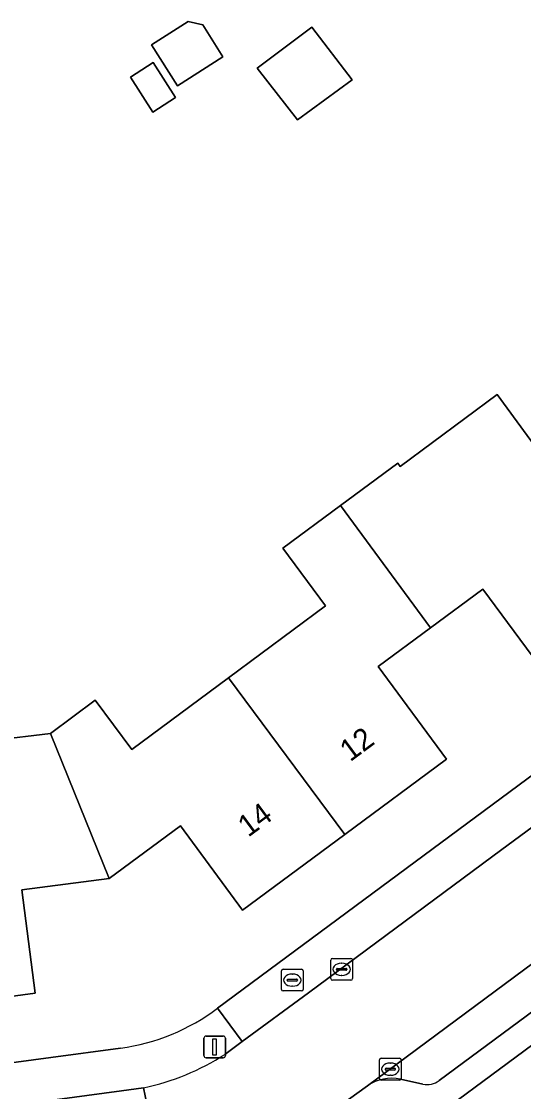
# Model space of a CAD drawing. Extents: x 163426 to 164192, y 380329 to 381641.
# Drawn here: x 163640.74 to 163663.86, y 381284.84 to 381334.09 of the extents above; entities that cross this region are included whole.
import ezdxf

# ---------------------------------------------------------------- set-up
doc = ezdxf.new("R2010")
doc.units = 0
for name, color, linetype in [('IMGEO_Brandkraan', 7, 'Continuous'), ('IMGEO_Erf', 7, 'Continuous'), ('IMGEO_Kolk', 7, 'Continuous'), ('IMGEO_Lichtmast', 7, 'Continuous'), ('IMGEO_Pand', 7, 'Continuous'), ('IMGEO_Pand_nummerreeks', 7, 'Continuous'), ('IMGEO_Parkeervlak_open', 7, 'Continuous'), ('IMGEO_Rijbaan_lokaal_open', 7, 'Continuous'), ('IMGEO_Voetpad_open', 7, 'Continuous')]:
    doc.layers.add(name, color=color, linetype=linetype)

msp = doc.modelspace()

# ---------------------------------------------------------------- linework, layer by layer
at = {"layer": 'IMGEO_Brandkraan'}
for p, q in [((163652.71, 381289.542), (163652.71, 381290.394)), ((163652.785, 381290.468), (163653.637, 381290.468)), ((163653.198, 381290.248), (163653.223, 381290.248)), ((163653.711, 381290.394), (163653.711, 381289.542)), ((163652.969, 381289.962), (163652.969, 381289.974)), ((163653.407, 381289.925), (163653.009, 381289.925)), ((163653.012, 381290.011), (163653.41, 381290.011)), ((163653.221, 381289.688), (163653.196, 381289.688)), ((163653.453, 381289.974), (163653.453, 381289.962)), ((163653.637, 381289.468), (163652.785, 381289.468))]:
    msp.add_line(p, q, dxfattribs=at)
for points in [[(163652.71, 381289.542), (163652.71, 381290.394)], [(163652.785, 381290.468), (163653.637, 381290.468)], [(163653.711, 381290.394), (163653.711, 381289.542)], [(163653.637, 381289.468), (163652.785, 381289.468)]]:
    msp.add_lwpolyline(points, dxfattribs=at)
for centre, radius, start, end in [((163652.787, 381290.392), 0.0765, 91.552, 178.448), ((163652.787, 381290.392), 0.0765, 91.552, 178.448), ((163653.635, 381290.392), 0.0765, 1.552, 88.448), ((163653.635, 381290.392), 0.0765, 1.552, 88.448), ((163653.009, 381289.971), 0.0403, 85.8775, 175.7526), ((163653.006, 381289.961), 0.0366, 178.938, 274.7102), ((163653.41, 381289.968), 0.043, 264.8664, 352.4533), ((163653.414, 381289.973), 0.0386, 1.7309, 96.639), ((163652.787, 381289.544), 0.0765, 181.552, 268.448), ((163652.787, 381289.544), 0.0765, 181.552, 268.448), ((163653.635, 381289.544), 0.0765, 271.552, 358.448), ((163653.635, 381289.544), 0.0765, 271.552, 358.448)]:
    msp.add_arc(centre, radius, start, end, dxfattribs=at)
for centre, major_axis, ratio, start_param, end_param in [((163653.197, 381289.968), (-0.387, 0.002), 0.722429, 4.712389, 7.853982), ((163653.222, 381289.968), (-0.39, 0.002), 0.717154, 1.570796, 4.712389)]:
    msp.add_ellipse(centre, major_axis=major_axis, ratio=ratio, start_param=start_param, end_param=end_param, dxfattribs=at)
at = {"layer": 'IMGEO_Erf'}
for points in [[(163647.921, 381331.13), (163646.723, 381333.013), (163648.421, 381334.093), (163649.086, 381333.928), (163650.018, 381332.464)], [(163654.105, 381333.835), (163655.963, 381331.405), (163653.457, 381329.566), (163651.599, 381331.939)], [(163645.76, 381331.53), (163646.807, 381332.196), (163647.83, 381330.589), (163646.783, 381329.923)]]:
    msp.add_lwpolyline(points, close=True, dxfattribs=at)
for points in [[(163649.769, 381288.678), (163692.92, 381320.603), (163703.68, 381328.564)], [(163740.553, 381295.871), (163741.259, 381296.424), (163738.778, 381299.792), (163718.602, 381327.167), (163657.027, 381281.631)], [(163639.5, 381301.01), (163642.07, 381301.32), (163644.14, 381302.85), (163645.82, 381300.582), (163650.279, 381303.886), (163654.746, 381307.196), (163652.78, 381309.85), (163655.428, 381311.81), (163658.069, 381313.765), (163658.184, 381313.609), (163662.649, 381316.914), (163664.494, 381314.412)], [(163665.136, 381303.706), (163661.986, 381307.964), (163659.576, 381306.181), (163657.166, 381304.398), (163660.316, 381300.14), (163655.624, 381296.669), (163650.92, 381293.19), (163648.06, 381297.07), (163644.78, 381294.65), (163640.75, 381294.12), (163641.37, 381289.36), (163635.572, 381288.579)], [(163588.634, 381279.227), (163596.717, 381280.313), (163605.786, 381281.532), (163642.098, 381286.411), (163645.301, 381286.841)]]:
    msp.add_lwpolyline(points, dxfattribs=at)
msp.add_arc((163644.05, 381296.235), 9.477, 277.5829, 307.1168, dxfattribs=at)
at = {"layer": 'IMGEO_Kolk'}
for p, q in [((163654.982, 381290.038), (163654.982, 381290.89)), ((163655.057, 381290.964), (163655.909, 381290.964)), ((163655.47, 381290.744), (163655.495, 381290.744)), ((163655.983, 381290.89), (163655.983, 381290.038)), ((163655.241, 381290.458), (163655.241, 381290.47)), ((163655.679, 381290.421), (163655.281, 381290.421)), ((163655.284, 381290.507), (163655.682, 381290.507)), ((163655.493, 381290.184), (163655.468, 381290.184)), ((163655.725, 381290.47), (163655.725, 381290.458)), ((163655.909, 381289.964), (163655.057, 381289.964)), ((163657.224, 381285.443), (163657.224, 381286.295)), ((163657.299, 381286.369), (163658.151, 381286.369)), ((163657.712, 381286.149), (163657.737, 381286.149)), ((163658.225, 381286.295), (163658.225, 381285.443)), ((163657.483, 381285.863), (163657.483, 381285.875)), ((163657.921, 381285.826), (163657.523, 381285.826)), ((163657.526, 381285.912), (163657.924, 381285.912)), ((163657.967, 381285.875), (163657.967, 381285.863)), ((163658.151, 381285.369), (163657.299, 381285.369)), ((163657.735, 381285.589), (163657.71, 381285.589))]:
    msp.add_line(p, q, dxfattribs=at)
for points in [[(163654.982, 381290.038), (163654.982, 381290.89)], [(163655.057, 381290.964), (163655.909, 381290.964)], [(163655.983, 381290.89), (163655.983, 381290.038)], [(163655.909, 381289.964), (163655.057, 381289.964)], [(163657.224, 381285.443), (163657.224, 381286.295)], [(163657.299, 381286.369), (163658.151, 381286.369)], [(163658.225, 381286.295), (163658.225, 381285.443)], [(163658.151, 381285.369), (163657.299, 381285.369)]]:
    msp.add_lwpolyline(points, dxfattribs=at)
for centre, radius, start, end in [((163655.059, 381290.888), 0.0765, 91.552, 178.448), ((163655.059, 381290.888), 0.0765, 91.552, 178.448), ((163655.907, 381290.888), 0.0765, 1.552, 88.448), ((163655.907, 381290.888), 0.0765, 1.552, 88.448), ((163655.281, 381290.467), 0.0403, 85.8775, 175.7526), ((163655.278, 381290.457), 0.0366, 178.938, 274.7102), ((163655.682, 381290.464), 0.043, 264.8664, 352.4533), ((163655.686, 381290.469), 0.0386, 1.7309, 96.639), ((163655.059, 381290.04), 0.0765, 181.552, 268.448), ((163655.059, 381290.04), 0.0765, 181.552, 268.448), ((163655.907, 381290.04), 0.0765, 271.552, 358.448), ((163655.907, 381290.04), 0.0765, 271.552, 358.448), ((163657.301, 381286.293), 0.0765, 91.552, 178.448), ((163657.301, 381286.293), 0.0765, 91.552, 178.448), ((163658.149, 381286.293), 0.0765, 1.552, 88.448), ((163658.149, 381286.293), 0.0765, 1.552, 88.448), ((163657.523, 381285.872), 0.0403, 85.8775, 175.7526), ((163657.52, 381285.862), 0.0366, 178.938, 274.7102), ((163657.924, 381285.869), 0.043, 264.8664, 352.4533), ((163657.928, 381285.874), 0.0386, 1.7309, 96.639), ((163657.301, 381285.445), 0.0765, 181.552, 268.448), ((163657.301, 381285.445), 0.0765, 181.552, 268.448), ((163658.149, 381285.445), 0.0765, 271.552, 358.448), ((163658.149, 381285.445), 0.0765, 271.552, 358.448)]:
    msp.add_arc(centre, radius, start, end, dxfattribs=at)
for centre, major_axis, ratio, start_param, end_param in [((163655.469, 381290.464), (-0.387, 0.002), 0.722429, 4.712389, 7.853982), ((163655.494, 381290.464), (-0.39, 0.002), 0.717154, 1.570796, 4.712389), ((163657.711, 381285.869), (-0.387, 0.002), 0.722429, 4.712389, 7.853982), ((163657.736, 381285.869), (-0.39, 0.002), 0.717154, 1.570796, 4.712389)]:
    msp.add_ellipse(centre, major_axis=major_axis, ratio=ratio, start_param=start_param, end_param=end_param, dxfattribs=at)
at = {"layer": 'IMGEO_Lichtmast'}
for p, q in [((163649.137, 381286.491), (163649.137, 381287.291)), ((163649.137, 381287.291), (163649.137, 381286.491)), ((163649.237, 381287.391), (163650.027, 381287.391)), ((163650.027, 381287.391), (163649.237, 381287.391)), ((163650.127, 381287.291), (163650.127, 381286.491)), ((163650.127, 381286.491), (163650.127, 381287.291)), ((163650.027, 381286.391), (163649.237, 381286.391)), ((163649.237, 381286.391), (163650.027, 381286.391))]:
    msp.add_line(p, q, dxfattribs=at)
msp.add_lwpolyline([(163649.557, 381287.266), (163649.707, 381287.266), (163649.707, 381286.516), (163649.557, 381286.516), (163649.557, 381287.266)], dxfattribs=at)
for centre, start, end in [((163649.237, 381287.291), 90, 180), ((163649.237, 381287.291), 90, 180), ((163650.027, 381287.291), 0, 90), ((163650.027, 381287.291), 360, 90), ((163649.237, 381286.491), 180, 270), ((163649.237, 381286.491), 180, 270), ((163650.027, 381286.491), 270, 0), ((163650.027, 381286.491), 270, 0)]:
    msp.add_arc(centre, 0.1, start, end, dxfattribs=at)
at = {"layer": 'IMGEO_Pand'}
for points in [[(163649.086, 381333.928), (163648.421, 381334.093), (163646.723, 381333.013), (163647.921, 381331.13), (163650.018, 381332.464)], [(163654.105, 381333.835), (163651.599, 381331.939), (163653.457, 381329.566), (163655.963, 381331.405)], [(163645.76, 381331.53), (163646.783, 381329.923), (163647.83, 381330.589), (163646.807, 381332.196)], [(163664.494, 381314.412), (163662.649, 381316.914), (163658.184, 381313.609), (163658.069, 381313.765), (163655.428, 381311.81), (163659.576, 381306.181), (163661.986, 381307.964), (163665.136, 381303.706), (163669.828, 381307.177)], [(163655.624, 381296.669), (163660.316, 381300.14), (163657.166, 381304.398), (163659.576, 381306.181), (163655.428, 381311.81), (163652.78, 381309.85), (163654.746, 381307.196), (163650.279, 381303.886)], [(163650.279, 381303.886), (163645.82, 381300.582), (163644.14, 381302.85), (163642.07, 381301.32), (163644.78, 381294.65), (163648.06, 381297.07), (163650.92, 381293.19), (163655.624, 381296.669)], [(163642.07, 381301.32), (163639.5, 381301.01), (163639.372, 381301.961), (163633.908, 381301.222), (163633.97, 381300.741), (163634.391, 381297.478), (163635.572, 381288.579), (163641.37, 381289.36), (163640.75, 381294.12), (163644.78, 381294.65)]]:
    msp.add_lwpolyline(points, close=True, dxfattribs=at)
at = {"layer": 'IMGEO_Parkeervlak_open'}
for points in [[(163710.833, 381325.231), (163656.677, 381285.107)], [(163659.971, 381285.341), (163672.822, 381294.849), (163675.849, 381297.088), (163684.721, 381303.652), (163690.817, 381308.162), (163698.807, 381314.074), (163704.911, 381318.588), (163709.791, 381322.2)], [(163658.194, 381285.401), (163659.227, 381285.18)]]:
    msp.add_lwpolyline(points, dxfattribs=at)
for centre, radius, start, end in [((163657.771, 381283.524), 1.924, 77.2983, 124.638), ((163659.421, 381286.081), 0.922, 257.8151, 306.6057)]:
    msp.add_arc(centre, radius, start, end, dxfattribs=at)
at = {"layer": 'IMGEO_Rijbaan_lokaal_open'}
for points in [[(163656.677, 381285.107), (163710.833, 381325.231), (163712.71, 381326.586), (163715.289, 381328.447), (163711.359, 381331.806), (163694.161, 381319.1), (163691.113, 381316.849), (163682.665, 381310.607), (163677.183, 381306.556), (163668.338, 381300.021), (163662.864, 381295.976), (163653.949, 381289.389), (163650.902, 381287.137), (163650.108, 381286.551)], [(163638.12, 381278.876), (163641.866, 381279.344), (163647.21, 381280.954), (163646.365, 381285.009), (163645.343, 381284.872), (163641.583, 381284.366), (163630.219, 381282.832), (163623.472, 381281.919), (163613.137, 381280.536), (163607.081, 381279.743), (163589.884, 381277.411)], [(163646.365, 381285.009), (163647.21, 381280.954), (163654.075, 381283.021), (163655.038, 381283.926), (163656.677, 381285.107)]]:
    msp.add_lwpolyline(points, dxfattribs=at)
msp.add_arc((163644.023, 381296.008), 11.246, 282.021, 302.7593, dxfattribs=at)
at = {"layer": 'IMGEO_Voetpad_open'}
msp.add_lwpolyline([(163682.665, 381310.607), (163691.113, 381316.849), (163694.161, 381319.1), (163711.359, 381331.806), (163710.193, 381333.382), (163703.68, 381328.564), (163692.92, 381320.603), (163649.769, 381288.678), (163650.902, 381287.137), (163653.949, 381289.389), (163662.864, 381295.976), (163668.338, 381300.021), (163677.183, 381306.556)], close=True, dxfattribs=at)
for points in [[(163657.027, 381281.631), (163718.602, 381327.167)], [(163709.791, 381322.2), (163704.911, 381318.588), (163698.807, 381314.074), (163690.817, 381308.162), (163684.721, 381303.652), (163675.849, 381297.088), (163672.822, 381294.849), (163659.971, 381285.341)], [(163650.108, 381286.551), (163650.902, 381287.137), (163649.769, 381288.678)], [(163645.301, 381286.841), (163642.098, 381286.411), (163605.786, 381281.532), (163596.717, 381280.313), (163588.634, 381279.227)], [(163659.227, 381285.18), (163658.194, 381285.401)], [(163641.583, 381284.366), (163645.343, 381284.872), (163646.365, 381285.009)], [(163656.677, 381285.107), (163655.038, 381283.926), (163654.075, 381283.021), (163655.852, 381278.964)]]:
    msp.add_lwpolyline(points, dxfattribs=at)
for centre, radius, start, end in [((163644.05, 381296.235), 9.477, 277.5829, 307.1168), ((163644.023, 381296.008), 11.246, 282.021, 302.7593), ((163657.771, 381283.524), 1.924, 77.2983, 124.638), ((163659.421, 381286.081), 0.922, 257.8151, 306.6057)]:
    msp.add_arc(centre, radius, start, end, dxfattribs=at)

# ---------------------------------------------------------------- texts
at = {"layer": 'IMGEO_Pand_nummerreeks'}
for s, p in [('12', (163655.874, 381299.99)), ('14', (163651.179, 381296.516))]:
    msp.add_text(s, height=1, rotation=36.4895, dxfattribs=at).set_placement(p)

doc.saveas('drawing.dxf')
